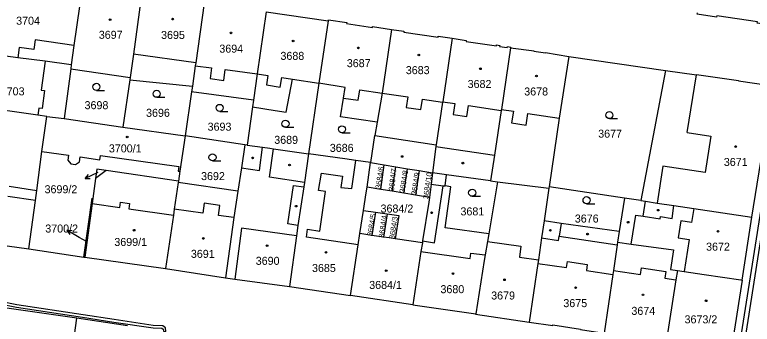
# Model space of a CAD drawing. Extents: x -756746 to -753363, y -1166406 to -1161727.
# Drawn here: x -755498.1 to -755341.5, y -1165582.7 to -1165517 of the extents above; entities that cross this region are included whole.
import ezdxf

# ---------------------------------------------------------------- set-up
doc = ezdxf.new("R2010")
doc.units = 0
for name, color, linetype in [('Hranice parcel', 7, 'Continuous'), ('Parcelní čísla', 7, 'Continuous'), ('Pop  PČ popisy', 7, 'Continuous'), ('Vnitřní kresba', 7, 'Continuous'), ('Věcná břemena k části', 7, 'Continuous'), ('Značky budov', 7, 'Continuous'), ('Značky kultur', 7, 'Continuous')]:
    doc.layers.add(name, color=color, linetype=linetype)

msp = doc.modelspace()

# ---------------------------------------------------------------- linework, layer by layer
at = {"layer": 'Hranice parcel'}
for p, q in [((-755444.77, -1165516.36), (-755431.57, -1165518.3)), ((-755431.57, -1165518.3), (-755433.57, -1165531.53)), ((-755380.5, -1165525.82), (-755359.97, -1165528.79)), ((-755486.24, -1165528.47), (-755487.62, -1165539.02)), ((-755486.13, -1165527.63), (-755486.24, -1165528.47)), ((-755486.24, -1165528.47), (-755473.63, -1165530.32)), ((-755359.97, -1165528.79), (-755365.14, -1165556.43)), ((-755473.63, -1165530.32), (-755473.7, -1165530.78)), ((-755473.7, -1165530.78), (-755475.17, -1165540.84)), ((-755473.7, -1165530.78), (-755460.42, -1165532.14)), ((-755460.42, -1165532.14), (-755460.59, -1165533.35)), ((-755433.57, -1165531.53), (-755435.73, -1165546.49)), ((-755460.59, -1165533.35), (-755461.92, -1165542.69)), ((-755447.44, -1165535.11), (-755460.59, -1165533.35)), ((-755447.44, -1165535.11), (-755447.64, -1165536.54)), ((-755447.64, -1165536.54), (-755448.77, -1165544.66)), ((-755491.35, -1165538.54), (-755487.62, -1165539.02)), ((-755487.62, -1165539.02), (-755475.17, -1165540.84)), ((-755475.17, -1165540.84), (-755461.92, -1165542.69)), ((-755449.28, -1165544.58), (-755461.92, -1165542.69)), ((-755448.77, -1165544.66), (-755449.28, -1165544.58)), ((-755423.31, -1165553.55), (-755422.57, -1165548.35)), ((-755422.57, -1165548.35), (-755419.68, -1165548.83)), ((-755420.42, -1165554.03), (-755419.68, -1165548.83)), ((-755419.68, -1165548.83), (-755417.21, -1165549.24)), ((-755417.95, -1165554.44), (-755417.21, -1165549.24)), ((-755417.21, -1165549.24), (-755414.75, -1165549.65)), ((-755478.69, -1165550.03), (-755480.97, -1165551.74)), ((-755463.36, -1165552.28), (-755478.69, -1165550.03)), ((-755415.48, -1165554.84), (-755414.75, -1165549.65)), ((-755414.75, -1165549.65), (-755412.28, -1165550.06)), ((-755412.28, -1165550.06), (-755413.01, -1165555.25)), ((-755412.28, -1165550.06), (-755409.39, -1165550.54)), ((-755406.43, -1165550.95), (-755409.39, -1165550.54)), ((-755397.09, -1165552.22), (-755406.43, -1165550.95)), ((-755480.97, -1165551.74), (-755481.55, -1165555.95)), ((-755463.36, -1165552.28), (-755463.4, -1165552.57)), ((-755450.75, -1165554.39), (-755463.4, -1165552.57)), ((-755395.61, -1165552.42), (-755397.49, -1165563.45)), ((-755397.09, -1165552.22), (-755395.61, -1165552.42)), ((-755395.61, -1165552.42), (-755384.69, -1165553.78)), ((-755420.42, -1165554.03), (-755423.31, -1165553.55)), ((-755417.95, -1165554.44), (-755420.42, -1165554.03)), ((-755384.69, -1165553.78), (-755385.72, -1165560.74)), ((-755384.65, -1165553.5), (-755384.69, -1165553.78)), ((-755368.67, -1165555.9), (-755384.65, -1165553.5)), ((-755415.48, -1165554.84), (-755417.95, -1165554.44)), ((-755413.01, -1165555.25), (-755415.48, -1165554.84)), ((-755410.07, -1165555.73), (-755413.01, -1165555.25)), ((-755368.67, -1165555.9), (-755369.78, -1165562.99)), ((-755365.14, -1165556.43), (-755368.67, -1165555.9)), ((-755424.87, -1165563.43), (-755424.08, -1165558.49)), ((-755424.08, -1165558.49), (-755421.5, -1165558.87)), ((-755421.5, -1165558.87), (-755422.3, -1165563.8)), ((-755421.5, -1165558.87), (-755419.02, -1165559.23)), ((-755419.02, -1165559.23), (-755419.81, -1165564.16)), ((-755343.68, -1165573.3), (-755341.59, -1165559.91)), ((-755422.3, -1165563.8), (-755424.87, -1165563.43)), ((-755369.78, -1165562.99), (-755370.13, -1165565.25)), ((-755510.24, -1165564.51), (-755495.11, -1165566.68)), ((-755419.81, -1165564.16), (-755422.3, -1165563.8)), ((-755495.11, -1165566.68), (-755483.43, -1165568.41)), ((-755483.43, -1165568.41), (-755483.27, -1165568.43)), ((-755483.27, -1165568.43), (-755466.14, -1165570.83)), ((-755466.14, -1165570.83), (-755453.41, -1165572.81)), ((-755343.68, -1165573.3), (-755346.01, -1165588.32)), ((-755439.82, -1165574.68), (-755426.85, -1165576.54)), ((-755413.61, -1165578.51), (-755426.85, -1165576.54)), ((-755484.93, -1165581.4), (-755510.57, -1165577.72)), ((-755413.61, -1165578.51), (-755400.24, -1165580.43)), ((-755474.21, -1165582.97), (-755484.93, -1165581.4))]:
    msp.add_line(p, q, dxfattribs=at)
for points in [[(-755483.75, -1165510.78), (-755485.58, -1165523.47), (-755486.13, -1165527.63)], [(-755471.24, -1165512.69), (-755472.91, -1165525.36), (-755473.63, -1165530.32)], [(-755457.9, -1165514.53), (-755459.71, -1165527.2), (-755459.8, -1165527.82), (-755460.42, -1165532.14)], [(-755444.77, -1165516.36), (-755446.66, -1165529.49), (-755447.44, -1165535.11)], [(-755334.75, -1165518.01), (-755336.51, -1165519.33), (-755340.45, -1165518.75), (-755340.41, -1165518.5), (-755349.05, -1165517.23), (-755349.08, -1165517.48), (-755353.21, -1165516.87), (-755353.17, -1165516.59)], [(-755431.57, -1165518.3), (-755431.53, -1165518.06), (-755427.62, -1165518.65), (-755427.65, -1165518.83), (-755422.18, -1165519.65), (-755422.15, -1165519.48), (-755418.16, -1165520.08)], [(-755418.16, -1165520.08), (-755420.14, -1165533.59), (-755421.17, -1165539.79)], [(-755418.16, -1165520.08), (-755415.48, -1165520.47), (-755415.51, -1165520.68), (-755408.23, -1165521.74), (-755408.2, -1165521.54), (-755405.27, -1165521.97)], [(-755405.27, -1165521.97), (-755407.25, -1165535.46), (-755407.27, -1165535.56), (-755408.63, -1165544.6), (-755408.68, -1165544.96), (-755409.39, -1165550.54)], [(-755405.27, -1165521.97), (-755402.24, -1165522.42), (-755402.27, -1165522.63), (-755395.84, -1165523.6), (-755395.81, -1165523.38), (-755395.13, -1165523.48), (-755395.17, -1165523.7), (-755393.55, -1165523.94), (-755393.52, -1165523.72), (-755392.79, -1165523.83), (-755392.82, -1165523.97)], [(-755392.82, -1165523.97), (-755394.8, -1165537.08), (-755394.83, -1165537.33), (-755396.25, -1165546.75), (-755397.09, -1165552.22)], [(-755392.82, -1165523.97), (-755387.86, -1165524.62), (-755387.87, -1165524.72), (-755385.44, -1165525.08), (-755385.43, -1165524.98), (-755380.5, -1165525.82)], [(-755486.13, -1165527.63), (-755491.7, -1165526.85), (-755497.47, -1165526.09), (-755504.73, -1165525.12)], [(-755380.5, -1165525.82), (-755382.49, -1165538.92), (-755384.65, -1165553.5)], [(-755359.97, -1165528.79), (-755353.35, -1165529.75), (-755353.33, -1165529.65), (-755344.42, -1165530.9), (-755344.43, -1165531), (-755337.17, -1165532.08)], [(-755447.64, -1165536.54), (-755442.83, -1165537.29), (-755440.51, -1165537.66), (-755439.17, -1165530.66), (-755433.57, -1165531.53)], [(-755421.17, -1165539.79), (-755428.94, -1165538.66), (-755428.3, -1165534.66), (-755427.95, -1165532.4), (-755433.57, -1165531.53)], [(-755341.59, -1165559.91), (-755339.7, -1165548.09), (-755339.4, -1165548.14), (-755338.71, -1165543.78), (-755339, -1165543.73), (-755337.17, -1165532.08)], [(-755491.35, -1165538.54), (-755493.22, -1165538.27), (-755506.29, -1165536.42)], [(-755495.11, -1165566.68), (-755493.74, -1165556.41), (-755493.45, -1165554.26), (-755492.35, -1165546.02), (-755491.35, -1165538.54)], [(-755421.17, -1165539.79), (-755421.68, -1165542.63), (-755421.76, -1165542.62), (-755422.57, -1165548.35)], [(-755461.92, -1165542.69), (-755463.05, -1165550.18), (-755463.36, -1165552.28)], [(-755449.28, -1165544.58), (-755450.01, -1165549.44), (-755450.75, -1165554.39)], [(-755448.77, -1165544.66), (-755445.54, -1165545.09), (-755443.94, -1165545.3), (-755443.18, -1165545.41), (-755435.73, -1165546.49)], [(-755435.73, -1165546.49), (-755436.63, -1165552.55), (-755436.77, -1165553.52), (-755437.99, -1165561.68), (-755438.32, -1165563.9), (-755439.82, -1165574.68)], [(-755422.57, -1165548.35), (-755425.73, -1165547.9), (-755428.02, -1165547.58), (-755435.73, -1165546.49)], [(-755478.69, -1165550.03), (-755480.7, -1165549.74), (-755480.97, -1165551.74)], [(-755409.39, -1165550.54), (-755409.7, -1165552.93), (-755410.07, -1165555.73)], [(-755397.49, -1165563.45), (-755406.72, -1165562.23), (-755405.5, -1165553.48), (-755406.75, -1165553.32), (-755406.43, -1165550.95)], [(-755463.4, -1165552.57), (-755464.25, -1165558.21), (-755464.44, -1165559.48), (-755466.14, -1165570.83)], [(-755424.08, -1165558.49), (-755423.48, -1165554.74), (-755423.31, -1165553.55)], [(-755450.75, -1165554.39), (-755451.59, -1165560.03), (-755453.41, -1165572.81)], [(-755410.07, -1165555.73), (-755410.2, -1165556.77), (-755411.54, -1165564.95), (-755411.57, -1165565.36)], [(-755483.43, -1165568.41), (-755481.71, -1165555.93), (-755481.55, -1165555.95)], [(-755481.55, -1165555.95), (-755481.7, -1165557.06), (-755483.27, -1165568.43)], [(-755365.14, -1165556.43), (-755364.19, -1165556.57), (-755361.72, -1165556.94), (-755358.14, -1165557.47), (-755353.92, -1165558.09), (-755341.59, -1165559.91)], [(-755419.02, -1165559.23), (-755416.55, -1165559.59), (-755417.32, -1165564.52)], [(-755385.72, -1165560.74), (-755386.24, -1165564.32), (-755386.93, -1165568.99), (-755387.05, -1165569.76), (-755388.88, -1165582.19)], [(-755369.78, -1165562.99), (-755382.12, -1165561.25), (-755385.72, -1165560.74)], [(-755426.85, -1165576.54), (-755425.23, -1165565.8), (-755424.87, -1165563.43)], [(-755397.49, -1165563.45), (-755397.77, -1165565.12), (-755398.23, -1165567.96), (-755398.42, -1165569.12), (-755400.24, -1165580.43)], [(-755417.32, -1165564.52), (-755418.59, -1165564.34), (-755419.81, -1165564.16)], [(-755411.57, -1165565.36), (-755413.92, -1165565.02), (-755417.32, -1165564.52)], [(-755411.57, -1165565.36), (-755411.91, -1165567.22), (-755413.61, -1165578.51)], [(-755370.13, -1165565.25), (-755370.21, -1165565.82), (-755371, -1165571.24), (-755371.13, -1165572.1), (-755372.97, -1165584.55)], [(-755370.13, -1165565.25), (-755367.21, -1165565.7), (-755358.21, -1165566.88), (-755358.88, -1165571.03), (-755357.41, -1165571.27)], [(-755357.41, -1165571.27), (-755357.71, -1165573.21), (-755359.78, -1165586.49)], [(-755357.41, -1165571.27), (-755355.98, -1165571.49), (-755351.73, -1165572.1), (-755343.93, -1165573.26), (-755343.68, -1165573.3)], [(-755453.41, -1165572.81), (-755451.4, -1165573.09), (-755439.82, -1165574.68)], [(-755400.24, -1165580.43), (-755400.26, -1165580.53), (-755388.88, -1165582.19)], [(-755486.86, -1165594.94), (-755486.15, -1165590.17), (-755484.93, -1165581.4)], [(-755388.88, -1165582.19), (-755383.88, -1165582.93), (-755383.86, -1165582.8), (-755377.97, -1165583.68), (-755377.99, -1165583.81), (-755372.97, -1165584.55)]]:
    msp.add_lwpolyline(points, dxfattribs=at)
at = {"layer": 'Pop  PČ popisy'}
for p, q in [((-755480.47, -1165550.49), (-755483.21, -1165551.71)), ((-755483.21, -1165551.71), (-755482.5, -1165550.85)), ((-755483.21, -1165551.71), (-755482.09, -1165551.76)), ((-755484.45, -1165564.22), (-755487.05, -1165562.72)), ((-755487.05, -1165562.72), (-755485.93, -1165562.79)), ((-755487.05, -1165562.72), (-755486.43, -1165563.65)), ((-755482.9, -1165565.1), (-755484.45, -1165564.22))]:
    msp.add_line(p, q, dxfattribs=at)
at = {"layer": 'Vnitřní kresba'}
for p, q in [((-755493.82, -1165522.28), (-755494.07, -1165524.38)), ((-755485.58, -1165523.47), (-755493.82, -1165522.28)), ((-755497.21, -1165523.95), (-755497.47, -1165526.09)), ((-755494.07, -1165524.38), (-755497.21, -1165523.95)), ((-755459.71, -1165527.2), (-755472.91, -1165525.36)), ((-755491.7, -1165526.85), (-755492.51, -1165532.97)), ((-755459.8, -1165527.82), (-755456.35, -1165528.26)), ((-755456.35, -1165528.26), (-755456.64, -1165530.53)), ((-755453.71, -1165530.91), (-755453.42, -1165528.63)), ((-755453.42, -1165528.63), (-755446.66, -1165529.49)), ((-755456.64, -1165530.53), (-755453.71, -1165530.91)), ((-755446.66, -1165529.49), (-755444.37, -1165529.85)), ((-755444.37, -1165529.85), (-755444.69, -1165531.88)), ((-755441.77, -1165532.31), (-755441.45, -1165530.3)), ((-755441.45, -1165530.3), (-755439.17, -1165530.66)), ((-755355.36, -1165541.98), (-755353.35, -1165529.75)), ((-755444.69, -1165531.88), (-755441.77, -1165532.31)), ((-755492.51, -1165532.97), (-755491.83, -1165533.06)), ((-755491.83, -1165533.06), (-755492.31, -1165536.89)), ((-755425.18, -1165535.13), (-755424.83, -1165532.88)), ((-755424.83, -1165532.88), (-755420.14, -1165533.59)), ((-755420.14, -1165533.59), (-755414.65, -1165534.43)), ((-755428.3, -1165534.66), (-755425.18, -1165535.13)), ((-755414.65, -1165534.43), (-755415.02, -1165536.66)), ((-755411.9, -1165537.11), (-755411.55, -1165534.91)), ((-755411.55, -1165534.91), (-755407.27, -1165535.56)), ((-755493.02, -1165536.8), (-755493.22, -1165538.27)), ((-755492.31, -1165536.89), (-755493.02, -1165536.8)), ((-755415.02, -1165536.66), (-755411.9, -1165537.11)), ((-755407.25, -1165535.46), (-755404.68, -1165535.84)), ((-755404.68, -1165535.84), (-755405.01, -1165538.13)), ((-755402.15, -1165538.55), (-755401.8, -1165536.27)), ((-755401.8, -1165536.27), (-755394.83, -1165537.33)), ((-755405.01, -1165538.13), (-755402.15, -1165538.55)), ((-755394.8, -1165537.08), (-755392.25, -1165537.46)), ((-755392.25, -1165537.46), (-755392.62, -1165539.94)), ((-755389.56, -1165540.4), (-755389.19, -1165537.92)), ((-755389.19, -1165537.92), (-755382.49, -1165538.92)), ((-755392.62, -1165539.94), (-755389.56, -1165540.4)), ((-755421.68, -1165542.63), (-755408.63, -1165544.6)), ((-755355.36, -1165541.98), (-755350.32, -1165542.76)), ((-755350.32, -1165542.76), (-755351.54, -1165550.47)), ((-755492.35, -1165546.02), (-755486.71, -1165546.78)), ((-755446.18, -1165550.01), (-755445.54, -1165545.09)), ((-755444.05, -1165551.44), (-755443.18, -1165545.41)), ((-755408.68, -1165544.96), (-755396.25, -1165546.75)), ((-755486.71, -1165546.78), (-755486.87, -1165547.81)), ((-755486.87, -1165547.81), (-755486.23, -1165548.63)), ((-755484.38, -1165548.18), (-755484.23, -1165547.14)), ((-755484.23, -1165547.14), (-755480.07, -1165547.76)), ((-755480.07, -1165547.76), (-755479.93, -1165546.83)), ((-755479.93, -1165546.83), (-755463.32, -1165549.15)), ((-755426.58, -1165553.85), (-755425.73, -1165547.9)), ((-755486.23, -1165548.63), (-755485.23, -1165548.77)), ((-755485.23, -1165548.77), (-755484.38, -1165548.18)), ((-755463.32, -1165549.15), (-755463.46, -1165550.14)), ((-755450.01, -1165549.44), (-755446.18, -1165550.01)), ((-755360.51, -1165549.09), (-755361.72, -1165556.94)), ((-755351.54, -1165550.47), (-755360.51, -1165549.09)), ((-755463.46, -1165550.14), (-755463.05, -1165550.18)), ((-755433.63, -1165554.28), (-755433.02, -1165550.58)), ((-755433.02, -1165550.58), (-755428.53, -1165551.22)), ((-755436.63, -1165552.55), (-755444.05, -1165551.44)), ((-755428.53, -1165551.22), (-755428.87, -1165553.63)), ((-755499.33, -1165553.38), (-755493.45, -1165554.26)), ((-755440.17, -1165561.36), (-755438.95, -1165553.19)), ((-755438.95, -1165553.19), (-755436.77, -1165553.52)), ((-755428.87, -1165553.63), (-755426.58, -1165553.85)), ((-755409.7, -1165552.93), (-755407.17, -1165553.26)), ((-755408.97, -1165565.35), (-755407.17, -1165553.26)), ((-755407.17, -1165553.26), (-755406.75, -1165553.32)), ((-755493.74, -1165556.41), (-755499.58, -1165555.57)), ((-755432.13, -1165554.51), (-755433.63, -1165554.28)), ((-755433.35, -1165562.89), (-755432.13, -1165554.51)), ((-755481.7, -1165557.06), (-755475.83, -1165557.88)), ((-755475.83, -1165557.88), (-755475.67, -1165556.78)), ((-755475.67, -1165556.78), (-755473.75, -1165557.06)), ((-755473.75, -1165557.06), (-755473.9, -1165558.15)), ((-755457.91, -1165556.96), (-755458.21, -1165559.08)), ((-755454.6, -1165557.48), (-755457.91, -1165556.96)), ((-755364.67, -1165559.75), (-755364.19, -1165556.57)), ((-755473.9, -1165558.15), (-755464.44, -1165559.48)), ((-755458.21, -1165559.08), (-755464.25, -1165558.21)), ((-755454.9, -1165559.55), (-755454.6, -1165557.48)), ((-755358.54, -1165560.19), (-755358.14, -1165557.47)), ((-755353.92, -1165558.09), (-755354.38, -1165561.06)), ((-755451.59, -1165560.03), (-755454.9, -1165559.55)), ((-755367.21, -1165565.7), (-755366.22, -1165559.52)), ((-755366.22, -1165559.52), (-755364.67, -1165559.75)), ((-755364.67, -1165559.75), (-755361.08, -1165560.27)), ((-755361.08, -1165560.27), (-755361.01, -1165559.83)), ((-755361.01, -1165559.83), (-755358.54, -1165560.19)), ((-755437.99, -1165561.68), (-755440.17, -1165561.36)), ((-755382.12, -1165561.25), (-755382.52, -1165563.96)), ((-755356.68, -1165560.71), (-755357.24, -1165564.33)), ((-755354.38, -1165561.06), (-755356.68, -1165560.71)), ((-755450, -1165562.25), (-755451.4, -1165573.09)), ((-755438.32, -1165563.9), (-755450, -1165562.25)), ((-755436.2, -1165564.2), (-755435.94, -1165562.5)), ((-755435.94, -1165562.5), (-755433.35, -1165562.89)), ((-755425.23, -1165565.8), (-755436.2, -1165564.2)), ((-755411.54, -1165564.95), (-755408.97, -1165565.35)), ((-755397.77, -1165565.12), (-755390.65, -1165566.08)), ((-755386.24, -1165564.32), (-755382.65, -1165564.86)), ((-755382.65, -1165564.86), (-755382.52, -1165563.96)), ((-755382.52, -1165563.96), (-755370.21, -1165565.82)), ((-755357.24, -1165564.33), (-755354.93, -1165564.69)), ((-755354.93, -1165564.69), (-755355.98, -1165571.49)), ((-755390.65, -1165566.08), (-755390.97, -1165568.45)), ((-755411.91, -1165567.22), (-755401.42, -1165568.7)), ((-755401.42, -1165568.7), (-755401.26, -1165567.55)), ((-755401.26, -1165567.55), (-755398.23, -1165567.96)), ((-755390.97, -1165568.45), (-755386.93, -1165568.99)), ((-755387.05, -1165569.76), (-755380.97, -1165570.65)), ((-755380.97, -1165570.65), (-755380.78, -1165569.36)), ((-755380.78, -1165569.36), (-755376.55, -1165569.98)), ((-755376.55, -1165569.98), (-755376.74, -1165571.27)), ((-755376.74, -1165571.27), (-755371.13, -1165572.1)), ((-755371, -1165571.24), (-755365.24, -1165572.09)), ((-755365.24, -1165572.09), (-755365.03, -1165570.72)), ((-755365.03, -1165570.72), (-755359.9, -1165571.5)), ((-755359.9, -1165571.5), (-755360.1, -1165572.85)), ((-755360.1, -1165572.85), (-755357.71, -1165573.21))]:
    msp.add_line(p, q, dxfattribs=at)
at = {"layer": 'Věcná břemena k části'}
for points in [[(-755359.28, -1165698), (-755359.38, -1165689.15), (-755359.05, -1165688.6), (-755345.68, -1165601.78), (-755346.55, -1165599.06), (-755344.92, -1165590.16), (-755343.89, -1165588.6), (-755343.3, -1165587.71), (-755335.52, -1165538.11), (-755335.58, -1165537.14), (-755334.93, -1165533.41), (-755334.97, -1165532.54), (-755335.04, -1165531.08), (-755335.65, -1165530.42), (-755333.98, -1165520.9), (-755332.49, -1165518.92), (-755332.43, -1165518.34), (-755331.84, -1165512.38)], [(-755333.45, -1165518.52), (-755334.92, -1165520.5), (-755336.73, -1165530.74), (-755336.02, -1165531.5), (-755335.98, -1165532.33), (-755335.93, -1165533.35), (-755336.58, -1165537.08), (-755336.52, -1165538.07), (-755344.26, -1165587.37), (-755344.99, -1165588.46), (-755345.86, -1165589.74), (-755347.59, -1165599.2)], [(-755504.75, -1165577.65), (-755497.74, -1165579.03), (-755483.72, -1165581.14), (-755477.11, -1165582.19), (-755468.76, -1165583.45), (-755466.9, -1165583.49), (-755466.64, -1165583.71), (-755466.56, -1165584.1), (-755466.06, -1165584.17), (-755466.15, -1165583.44), (-755466.72, -1165582.99), (-755468.72, -1165582.95), (-755477.03, -1165581.69), (-755483.64, -1165580.64), (-755497.66, -1165578.53), (-755504.73, -1165577.15)]]:
    msp.add_lwpolyline(points, dxfattribs=at)
at = {"layer": 'Značky budov'}
for centre in [(-755477.88, -1165518.02), (-755464.61, -1165517.91), (-755452.2, -1165520.83), (-755439.02, -1165522.53), (-755425.16, -1165524.01), (-755412.32, -1165525.51), (-755399.24, -1165528.44), (-755387.34, -1165529.98), (-755474.26, -1165542.92), (-755345.03, -1165544.95), (-755447.62, -1165547.36), (-755415.86, -1165547.06), (-755439.78, -1165548.88), (-755402.96, -1165548.46), (-755438.38, -1165557.6), (-755409.6, -1165559), (-755361.48, -1165558.45), (-755367.87, -1165561.01), (-755472.78, -1165562.7), (-755384.39, -1165562.72), (-755376.49, -1165563.54), (-755348.78, -1165562.94), (-755458.1, -1165564.45), (-755444.54, -1165565.97), (-755432.05, -1165567.41), (-755419.25, -1165571.3), (-755405.07, -1165571.91), (-755394.13, -1165573.23), (-755379.03, -1165574.91), (-755364.73, -1165576.42), (-755351.31, -1165577.69)]:
    msp.add_circle(centre, 0.175, dxfattribs=at)
at = {"layer": 'Značky kultur'}
for p, q in [((-755480.8, -1165533.03), (-755479.05, -1165533.03)), ((-755467.99, -1165534.5), (-755466.24, -1165534.5)), ((-755454.61, -1165537.5), (-755452.86, -1165537.5)), ((-755371.85, -1165539.02), (-755370.1, -1165539.02)), ((-755440.64, -1165540.87), (-755438.89, -1165540.87)), ((-755428.65, -1165542.03), (-755426.9, -1165542.03)), ((-755456.14, -1165547.99), (-755454.39, -1165547.99)), ((-755400.99, -1165555.51), (-755399.24, -1165555.51)), ((-755376.7, -1165557.08), (-755374.95, -1165557.08))]:
    msp.add_line(p, q, dxfattribs=at)
for centre in [(-755480.8, -1165532.28), (-755467.99, -1165533.75), (-755454.61, -1165536.75), (-755371.85, -1165538.27), (-755440.64, -1165540.12), (-755428.65, -1165541.28), (-755456.14, -1165547.24), (-755400.99, -1165554.76), (-755376.7, -1165556.33)]:
    msp.add_circle(centre, 0.75, dxfattribs=at)

# ---------------------------------------------------------------- texts
at = {"layer": 'Parcelní čísla'}
for s, p in [('3704', (-755497.84, -1165519.09)), ('3697', (-755480.29, -1165522.08)), ('3695', (-755467.06, -1165522.11)), ('3694', (-755454.69, -1165525.02)), ('3688', (-755441.71, -1165526.55)), ('3687', (-755427.62, -1165528.1)), ('3683', (-755415.09, -1165529.58)), ('3682', (-755401.96, -1165532.52)), ('3703', (-755501.11, -1165534.08)), ('3678', (-755389.94, -1165534.11)), ('3698', (-755483.31, -1165537.02)), ('3696', (-755470.25, -1165538.64)), ('3693', (-755457.18, -1165541.58)), ('3677', (-755374.23, -1165543.06)), ('3689', (-755443.03, -1165544.37)), ('3700/1', (-755478.15, -1165546.19)), ('3686', (-755431.23, -1165546.08)), ('3671', (-755347.55, -1165549.07)), ('3692', (-755458.57, -1165552.07)), ('3699/2', (-755491.8, -1165554.86)), ('3684/2', (-755420.45, -1165558.96)), ('3681', (-755403.48, -1165559.56)), ('3676', (-755379.2, -1165561.08)), ('3700/2', (-755491.65, -1165563.2)), ('3699/1', (-755476.99, -1165566.05)), ('3672', (-755351.32, -1165567.05)), ('3691', (-755460.73, -1165568.57)), ('3690', (-755446.96, -1165570.05)), ('3685', (-755435.01, -1165571.57)), ('3684/1', (-755422.86, -1165575.17)), ('3680', (-755407.73, -1165576.07)), ('3679', (-755396.96, -1165577.41)), ('3675', (-755381.63, -1165579.03)), ('3674', (-755367.18, -1165580.67)), ('3673/2', (-755355.89, -1165582.47))]:
    msp.add_text(s, height=1.7, dxfattribs=at).set_placement(p)
for s, rotation, p in [('3684/6', 81, (-755420.45, -1165554.02)), ('3684/7', 83, (-755417.62, -1165554.43)), ('3684/8', 81, (-755415.34, -1165554.84)), ('3684/9', 82, (-755412.8, -1165555.3)), ('3684/10', 82, (-755410.31, -1165556.15)), ('3684/5', 80, (-755422.23, -1165564.08)), ('3684/4', 82, (-755419.73, -1165564.4)), ('3684/3', 81, (-755417.53, -1165564.67))]:
    msp.add_text(s, height=1.139, rotation=rotation, dxfattribs=at).set_placement(p)

doc.saveas('drawing.dxf')
